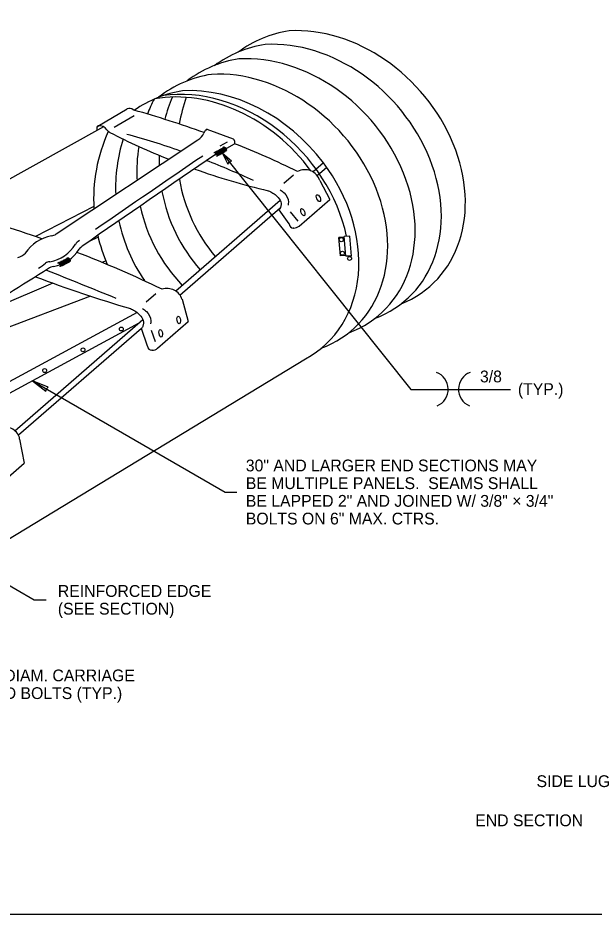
# Model space of a CAD drawing. Extents: x 99862 to 103151, y 100000 to 102076.
# Drawn here: x 101095 to 101876, y 100000 to 101215 of the extents above; entities that cross this region are included whole.
import ezdxf

# ---------------------------------------------------------------- set-up
doc = ezdxf.new("R2010")
doc.units = 0
for name, color, linetype in [('Level 1', 7, 'Continuous'), ('Level 15', 7, 'Continuous'), ('Level 18', 7, 'Continuous'), ('Level 20', 7, 'Continuous'), ('Level 6', 7, 'Continuous')]:
    doc.layers.add(name, color=color, linetype=linetype)

msp = doc.modelspace()

# ---------------------------------------------------------------- linework, layer by layer
at = {"layer": 'Level 1'}
for p, q in [((101225.3, 101066.7), (101252.5, 101082.5)), ((101378.5, 101046.1), (101368.6, 101040.9)), ((101455.5, 100990.5), (101468.4, 101001.8)), ((101464, 100951.6), (101474.5, 100938.9)), ((101268.8, 100829.5), (101281.8, 100840.8)), ((101281.4, 100775.4), (101276, 100790.7)), ((101375.8, 100571.8), (101391.8, 100571.8))]:
    msp.add_line(p, q, dxfattribs=at)
msp.add_lwpolyline([(99862, 99999.5), (103151, 99999.5), (103151, 102075.5), (99862, 102075.5)], close=True, dxfattribs=at)
for centre, radius, start, end in [((111586.5, 85957), 18220.8, 124.19844, 124.75241), ((101185, 100899.7), 14.6, 117.1984, 147.5625), ((101128.6, 100935.7), 52.4, 280.2147, 327.8332), ((100627.7, 101547.5), 834.9, 306.3613, 307.1698), ((101138.9, 100872.3), 11.9, 94.8755, 124.3016), ((124064.1, 157637.7), 61221.5, 248.003325, 248.098172)]:
    msp.add_arc(centre, radius, start, end, dxfattribs=at)
for points in [[(101450.4, 100981.7), (101455.8, 100977.3), (101461.5, 100964.9), (101461, 100961)], [(101263.8, 100820.7), (101269.2, 100816.4), (101275, 100804), (101274.5, 100800)]]:
    msp.add_spline(points, degree=3, dxfattribs=at)
at = {"layer": 'Level 15'}
for p, q in [((101372, 101030.8), (101627.4, 100710.9)), ((101114.6, 100722.6), (101375.8, 100571.8)), ((100963.8, 100514), (101116.9, 100425.6)), ((101116.9, 100425.6), (101132.9, 100425.6))]:
    msp.add_line(p, q, dxfattribs=at)
for points in [[(101372, 101030.8), (101379.4, 101016.6), (101381.4, 101019.1), (101384.3, 101020.5)], [(101114.6, 100722.6), (101132.8, 100708.6), (101133.4, 100711.7), (101135.8, 100713.8)]]:
    msp.add_lwpolyline(points, close=True, dxfattribs=at)
at = {"layer": 'Level 18'}
for p, q in [((101203, 101068.1), (101243.1, 101091.5)), ((101251.9, 101089.8), (101250.9, 101090.1)), ((101210.9, 101067), (101006.4, 100953.3)), ((101201.9, 101066.7), (101201.9, 101062)), ((101348.8, 101062.1), (101347, 101058.3)), ((101387, 101050.2), (101351.6, 101063.2)), ((101146.8, 100921.8), (101338.9, 101049.3)), ((101362.4, 101029.1), (101388.4, 101044.1)), ((101388.4, 101048), (101388.4, 101044.1)), ((101509.1, 101018.2), (101494.9, 101005.8)), ((101513.6, 101011.9), (101500.7, 101000.7)), ((101504.1, 100994.1), (101517.6, 100968.6)), ((101197.6, 100959), (101118.4, 100918.2)), ((101450.5, 100967.3), (101308.8, 100844.3)), ((101476.1, 100932.5), (101517.6, 100968.6)), ((101314.5, 100838.8), (101450.5, 100957)), ((101462.5, 100935.3), (101448.9, 100954.4)), ((101468.7, 100929.7), (101468.2, 100929.7)), ((101203.5, 100917.5), (101191.2, 100911.5)), ((101537.3, 100917.2), (101529.8, 100917.1)), ((101532, 100892.3), (101529.8, 100917.1)), ((101544.8, 100918.6), (101537.3, 100918.5)), ((101539.6, 100891.6), (101537.3, 100918.5)), ((101547.2, 100891.6), (101544.8, 100918.6)), ((101539.5, 100892.4), (101532, 100892.3)), ((101547.2, 100891.6), (101539.7, 100891.5)), ((101213.9, 100885.3), (101208.8, 100883.2)), ((101142.3, 100855), (101029.3, 100807.1)), ((101193.1, 100837.5), (100913.7, 100731.5)), ((101317.3, 100833.2), (101325.7, 100803)), ((101256.5, 100815.3), (101012, 100683)), ((101258.6, 100800.7), (101028.3, 100675.8)), ((101090.6, 100654.8), (101264.3, 100805.6)), ((101284.2, 100766.8), (101325.7, 100803)), ((101262.3, 100793.4), (101095.5, 100649)), ((101270.6, 100769.7), (101262.3, 100793.4)), ((101276.8, 100764), (101276.3, 100764)), ((100826.9, 100353.2), (101484.8, 100752.4)), ((101097.1, 100643.7), (101103.4, 100611.1)), ((101062, 100574.9), (101103.4, 100611.1))]:
    msp.add_line(p, q, dxfattribs=at)
for centre, radius in [((101533.2, 100914), 2.72), ((101534.8, 100895.5), 2.72), ((101544.4, 100888.5), 2.72), ((101235, 100792.8), 2.6), ((101183, 100764.7), 2.6), ((101131, 100736.5), 2.6)]:
    msp.add_circle(centre, radius, dxfattribs=at)
for centre, radius, start, end in [((101245.8, 101084.2), 7.78, 49.1974, 110.9464), ((100814.3, 99552.7), 1598.1, 70.511, 74.1083), ((101204.2, 101066), 2.47, 101.769, 161.913), ((101205.3, 101056.8), 11.7, 32.6893, 97.6667), ((101225.7, 101071.2), 13.3, 217.3317, 242.5226), ((101651.9, 101902.6), 947.6, 242.8386, 248.1551), ((100966, 100032.2), 1061.2, 70.7753, 74.9101), ((101326.7, 101068.2), 22.5, 302.6719, 333.9546), ((101350.9, 101061.1), 2.25, 71.3406, 153.1698), ((101386.1, 101048.1), 2.25, 354.2447, 68.8637), ((101004.1, 100054.9), 1061.2, 63.7257, 68.7728), ((101361.1, 101028), 3.73, 341.2962, 97.6706), ((101361.8, 101028.4), 3.73, 341.2962, 97.6706), ((101362.7, 101028.8), 3.73, 341.2962, 97.6706), ((101363.6, 101029.2), 3.73, 341.2962, 97.6706), ((101364.4, 101029.7), 3.73, 341.2962, 97.6706), ((101365.2, 101030.1), 3.73, 341.2962, 97.6706), ((101366, 101030.5), 3.73, 341.2962, 97.6706), ((101366.8, 101030.9), 3.73, 341.2962, 97.6706), ((101367.7, 101031.6), 3.73, 341.2962, 97.6706), ((101368.5, 101032), 3.73, 341.2962, 97.6706), ((101369.3, 101032.5), 3.73, 341.2962, 97.6706), ((101370.2, 101033.1), 3.73, 341.2962, 97.6706), ((101371.2, 101033.6), 3.73, 341.2962, 97.6706), ((101372, 101034.1), 3.73, 341.2962, 97.6706), ((101372.6, 101034.6), 3.73, 341.2962, 97.6706), ((101373.3, 101035.2), 3.73, 341.2962, 97.6706), ((101374.1, 101035.7), 3.73, 341.2962, 97.6706), ((111592.7, 85951.4), 18220.8, 124.1554, 124.84263), ((100966, 100032.2), 1061.2, 65.0292, 68.7728), ((101651.9, 101902.6), 947.6, 250.4298, 256.7032), ((101483.8, 100987.6), 21.3, 17.6879, 117.7933), ((100650.2, 99558.7), 1437.9, 70.6231, 75.4516), ((101468.2, 100935.3), 5.63, 180, 270), ((101468.7, 100941), 11.3, 270, 311.0698), ((101149, 100867), 52.8, 99.4432, 146.8387), ((101138.5, 100933), 14, 277.1017, 306.2885), ((101133.7, 100929.1), 52.4, 280.4125, 327.6558), ((101188.2, 100895), 11.9, 117.5487, 149.867), ((101086.9, 100914.2), 25.6, 287.9769, 314.4241), ((101155.6, 100881.7), 3.73, 337.6017, 93.9762), ((101156.4, 100882.2), 3.73, 337.6017, 93.9762), ((101157.3, 100882.6), 3.73, 337.6017, 93.9762), ((101158.2, 100883.1), 3.73, 337.6017, 93.9762), ((101159.2, 100883.5), 3.73, 337.6017, 93.9762), ((101160, 100884), 3.73, 337.6017, 93.9762), ((101160.7, 100884.4), 3.73, 337.6017, 93.9762), ((101161.4, 100885), 3.73, 337.6017, 93.9762), ((101162.2, 100885.5), 3.73, 337.6017, 93.9762), ((100661.3, 99553.6), 1437.9, 64.0654, 69.0773), ((125612.6, 62046.3), 45899.3, 122.22614, 122.5453), ((101144, 100865.6), 12, 94.301, 130.4773), ((101148.7, 100878.6), 3.73, 337.6017, 93.9762), ((101149.5, 100879), 3.73, 337.6017, 93.9762), ((101150.4, 100879.3), 3.73, 337.6017, 93.9762), ((101151.3, 100879.6), 3.73, 337.6017, 93.9762), ((101152.2, 100880), 3.73, 337.6017, 93.9762), ((101153, 100880.5), 3.73, 337.6017, 93.9762), ((101153.8, 100880.7), 3.73, 337.6017, 93.9762), ((101154.7, 100881.2), 3.73, 337.6017, 93.9762), ((101844, 102812.3), 2079.3, 249.581, 253.3216), ((101297, 100826.5), 21.3, 17.3206, 108.6436), ((101276.3, 100769.7), 5.63, 180, 270), ((101276.8, 100775.3), 11.3, 270, 311.0698), ((101076.9, 100638.5), 21.3, 25.0943, 116.8218), ((101086.8, 100643.4), 10.3, 0.7848, 23.4047)]:
    msp.add_arc(centre, radius, start, end, dxfattribs=at)
for centre, start_param, end_param in [((101357.5, 100920.4), 4.0706, 5.785957), ((101370, 100925.4), 2.943773, 4.587829)]:
    msp.add_ellipse(centre, major_axis=(-141.6, 153.8), ratio=0.796016, start_param=start_param, end_param=end_param, dxfattribs=at)
for centre, major_axis in [((101502.3, 100970.3), (2.13, -4.68)), ((101481.1, 100951.3), (1.85, -4.8)), ((101312.8, 100805), (0.78, -5.08)), ((101288.4, 100786.9), (0.78, -5.08))]:
    msp.add_ellipse(centre, major_axis=major_axis, ratio=0.443982, dxfattribs=at)
for points in [[(101433.1, 100980.6), (101435.9, 100979.7), (101447.6, 100971.1), (101451.6, 100963.4), (101451.5, 100962.8)], [(101451.2, 100958.8), (101450.6, 100957.2), (101449.7, 100955.7), (101448.9, 100954.4)], [(101451.5, 100962.8), (101451.5, 100960.8), (101451.1, 100958.8)], [(101247.3, 100820.5), (101250, 100819.4), (101261.4, 100810.2), (101265, 100802.4), (101265, 100801.9)], [(101265, 100801.9), (101264.9, 100799.8), (101264.5, 100797.9)], [(101264.6, 100797.9), (101264, 100796.2), (101263.1, 100794.8), (101262.3, 100793.4)]]:
    msp.add_spline(points, degree=3, dxfattribs=at)
at = {"layer": 'Level 20'}
msp.add_line((101627.4, 100710.9), (101762.8, 100710.9), dxfattribs=at)
for centre, start, end in [((101653.8, 100711.2), 292.7679, 69.5486), ((101716.5, 100711.2), 110.4514, 247.2321)]:
    msp.add_arc(centre, 24.4, start, end, dxfattribs=at)
at = {"layer": 'Level 6'}
for centre, radius, start, end in [((101485.5, 101045.7), 153.2, 98.652, 126.9089), ((101452.9, 101027.2), 153.2, 98.652, 126.7718), ((101417.4, 101007.7), 153.2, 98.652, 127.3603), ((101380.2, 100986.7), 153.2, 98.652, 128.213), ((101341.2, 100964.4), 153.2, 98.7433, 125.2662), ((101477.3, 101005.3), 221.4, 153.338, 159.1134), ((101507.7, 101020), 221.4, 156.7155, 165.0104), ((101531.8, 101033.6), 221.4, 160.6155, 170.3041), ((101418.8, 100969.1), 221.4, 155.5475, 183.4783), ((101448.6, 100984.2), 221.4, 162.5583, 182.3169), ((101477.3, 101005.3), 221.4, 170.868, 182.4192), ((101507.7, 101020), 221.4, 177.8459, 181.4309), ((101531.8, 101033.6), 221.4, 189.8764, 220.1196), ((101507.7, 101020), 221.4, 190.5692, 221.5505), ((101477.3, 101005.3), 221.4, 192.0107, 223.8397), ((101448.6, 100984.2), 221.4, 191.703, 214.6116), ((101418.8, 100969.1), 221.4, 192.931, 203.6321)]:
    msp.add_arc(centre, radius, start, end, dxfattribs=at)
for centre, start_param, end_param in [((101514.3, 101006.8), 2.84754, 5.706242), ((101481.7, 100988.3), 2.824672, 5.706242), ((101446.2, 100968.7), 2.8289, 5.706242), ((101409, 100947.8), 2.826961, 5.706242), ((101351.3, 100916.8), 4.57404, 5.813948), ((101370, 100925.4), 4.587829, 5.707457)]:
    msp.add_ellipse(centre, major_axis=(-141.6, 153.8), ratio=0.796016, start_param=start_param, end_param=end_param, dxfattribs=at)

# ---------------------------------------------------------------- texts
at = {"layer": 'Level 20'}
for s, p in [('3/8', (101721.3, 100720.5)), ('(TYP.)', (101772.7, 100703.4)), ('30" AND LARGER END SECTIONS MAY', (101403.8, 100599.8)), ('BE MULTIPLE PANELS.  SEAMS SHALL', (101403.8, 100575.8)), ('BE LAPPED 2" AND JOINED W/ 3/8" × 3/4"', (101403.8, 100551.8)), ('BOLTS ON 6" MAX. CTRS.', (101403.8, 100527.8)), ('REINFORCED EDGE', (101148.9, 100429.6)), ('(SEE SECTION)', (101148.9, 100405.6)), ('1/2" DIAM. CARRIAGE', (101032.9, 100315.1)), ('HEAD BOLTS (TYP.)', (101032.9, 100291.1)), ('SIDE LUG', (101798, 100171.7)), ('END SECTION', (101714.9, 100118.6))]:
    msp.add_text(s, height=16, dxfattribs=at).set_placement(p)

doc.saveas('drawing.dxf')
